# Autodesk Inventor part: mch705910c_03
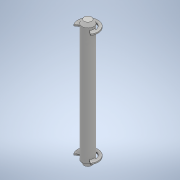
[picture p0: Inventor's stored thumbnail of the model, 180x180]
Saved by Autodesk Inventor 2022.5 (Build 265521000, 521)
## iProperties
Part Number: mch705910c_03
Material: 一般
Document SubType Name: Modeling
Designer: ImaoCorp
Density: 1 g/cm^3
Appearance: 既定
Author: ImaoCorp
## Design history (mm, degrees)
feature "mch705910c_03"
node "ソリッド1"
